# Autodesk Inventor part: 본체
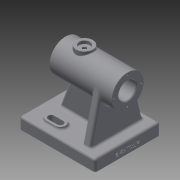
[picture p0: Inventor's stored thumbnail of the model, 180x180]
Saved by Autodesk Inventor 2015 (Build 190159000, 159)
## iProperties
Created: 2022-06
Part Number: 본체
Material: 일반
Document SubType Name: Modeling
Designer: 104-111
Density: 1 g/cm^3
Appearance: 기본값
Author: 104-111
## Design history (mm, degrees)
sketch "스케치1"
  geometry: L1 (0, 0)-(-100, 0); L2 (-100, 0)-(-100, 86); L3 (-100, 86)-(0, 86); L4 (0, 86)-(0, 0)
  constraints: 8 end point, 2 parallel, 1 horizontal, 1 perpendicular
  dimensions: "d0" = 100 distance of L1.start L1.end; "d1" = 86 distance of L3.end L1.start
extrude "돌출1" new body sketch "스케치1" distance "d2" = 15; taper "d3" = 0 deg
sketch "스케치2"
  geometry: L1 (0, 0)-(0, 86) reference; L2 (0, 86)-(-100, 86) reference; L3 (-100, 86)-(-100, 0) reference; L4 (-74, 70)-(-62, 70); L5 (-74, 63)-(-62, 63); L6 (-62, 77)-(-74, 77); L7 (-74, 16)-(-62, 16); L8 (-74, 9)-(-62, 9); L9 (-62, 23)-(-74, 23); L10 (-100, 43)-(0, 43); A1 r 7 centre (-74, 70) between (-74, 77) and (-74, 63); A2 r 7 centre (-62, 70) between (-62, 63) and (-62, 77); A3 r 7 centre (-74, 16) between (-74, 23) and (-74, 9); A4 r 7 centre (-62, 16) between (-62, 9) and (-62, 23); 2 further points
  constraints: 18 end point, 8 point on circle, 8 tangent, 4 centre point, 4 midpoint, 3 parallel, 1 horizontal
  dimensions: "d4" = 12 distance of L6.start L6.end; "d5" = 12 distance of L9.start L9.end; "d6" = 54 distance of point (-68, 16) point (-68, 70); "d7" = 16 distance from line of L2 point (-68, 70); "d8" = 26 distance from line of L3 L6.end; "d9" = 26 distance from line of L3 L8.start; "d10" = 14 distance between parallel lines of L6 L5; "d11" = 14 distance between parallel lines of L8 L9
extrude "돌출2" join sketch "스케치2" distance "d12" = 3; taper "d13" = 0 deg
sketch "스케치3"
  geometry: L1 (-74, 70)-(-62, 70); L2 (-74, 66)-(-62, 66); L3 (-62, 74)-(-74, 74); A1 r 7 centre (-62, 70) between (-62, 63) and (-62, 77) reference; A2 r 7 centre (-74, 70) between (-74, 77) and (-74, 63) reference; A3 r 4 centre (-74, 70) between (-74, 74) and (-74, 66); A4 r 4 centre (-62, 70) between (-62, 66) and (-62, 74); 2 further points
  constraints: 8 end point, 4 point on circle, 4 tangent, 2 centre point, 1 horizontal, 1 midpoint, 1 parallel
  dimensions: "d14" = 8 distance between parallel lines of L2 L3
extrude "돌출3" cut sketch "스케치3" stored distance "d15" = 3; taper "d16" = 0 deg
sketch "스케치4"
  geometry: L1 (-74, 16)-(-62, 16); L2 (-74, 20)-(-62, 20); L3 (-62, 12)-(-74, 12); A1 r 7 centre (-62, 16) between (-62, 9) and (-62, 23) reference; A2 r 7 centre (-74, 16) between (-74, 23) and (-74, 9) reference; A3 r 4 centre (-74, 16) between (-74, 20) and (-74, 12); A4 r 4 centre (-62, 16) between (-62, 12) and (-62, 20); 2 further points
  constraints: 8 end point, 4 point on circle, 4 tangent, 2 centre point, 1 horizontal, 1 midpoint, 1 parallel
  dimensions: "d17" = 8 distance between parallel lines of L2 L3
extrude "돌출4" cut sketch "스케치4" stored distance "d18" = 3; taper "d19" = 0 deg
sketch "스케치5"
  geometry: L1 (0, 0)-(0, 86) reference; L2 (-100, 86)-(-100, 0) reference; L3 (-85, 48)-(-15, 48); L4 (-15, 48)-(-15, 38); L5 (-15, 38)-(-85, 38); L6 (-85, 38)-(-85, 48); L7 (-100, 43)-(0, 43)
  constraints: 10 end point, 2 midpoint, 2 parallel, 1 horizontal, 1 perpendicular
  dimensions: "d20" = 10 distance between parallel lines of L5 L3; "d21" = 5 distance between parallel lines of L7 L3; "d22" = 15 distance between parallel lines of L2 L6; "d23" = 70 distance of L3.start L3.end
extrude "돌출5" join sketch "스케치5" distance "d24" = 57; taper "d25" = 0 deg
sketch "스케치6"
  geometry: L1 (-57, 0)-(-57, 10) reference; L2 (0, 0)-(-57, 0) reference; L3 (0, 48)-(0, -38) reference; L4 (15, -38)-(0, -38) reference; L5 (0, -38)-(0, 48) reference; L6 (-57, 5)-(21.35, 5); L7 (0, -30)-(-61.814, -15.441); L8 (0, 40)-(-61.814, 25.441); L9 (15, 48)-(0, 48) reference; L10 (-36, 0)-(0, 0); A1 r 21 centre (-57, 5) between (-61.814, -15.441) and (-61.814, 25.441); 1 further point
  constraints: 8 end point, 3 point on line, 2 horizontal, 2 point on circle, 2 tangent, 1 centre point, 1 midpoint
  dimensions: "d26" = 42 diameter of A1; "d28" = 8 distance from line of L9 L8.start; "d29" = 8 distance from line of L7.start L4
extrude "돌출6" join sketch "스케치6" distance "d30" = 10; taper "d31" = 0 deg
sketch "스케치7"
  geometry: C1 r 21 at (0, 5); A1 r 21 centre (0, 5) between (20.396, 10) and (-4.814, 25.441) reference; 1 further point
  constraints: 1 centre point, 1 coincident
  dimensions: "d32" = 42 diameter of C1
extrude "돌출7" join sketch "스케치7" distance "d33" = 15; taper "d35" = 0 deg; dims "d34" = 67, "d36" = 0
feature "면 기울기1" dims angle "d37" = 20 deg
sketch "스케치8"
  geometry: C1 r 21 at (0, 0) reference; C2 r 11.5 at (0, 0); 1 further point
  constraints: 1 centre point, 1 coincident
  dimensions: "d38" = 23 diameter of C2
extrude "돌출8" cut sketch "스케치8" distance "d39" = 20; taper "d40" = 0 deg
sketch "스케치9"
  geometry: C1 r 11.5 at (0, 0) reference; C2 r 14.5 at (0, 0); 1 further point
  constraints: 1 centre point, 1 coincident
  dimensions: "d41" = 29 diameter of C2
extrude "돌출9" cut sketch "스케치9" distance "d42" = 62; taper "d43" = 0 deg
sketch "스케치10"
  geometry: C1 r 11.5 at (0, 0) reference; 2 further points
  constraints: 1 horizontal alignment
  dimensions: "d44" = 18 distance of point (-18, 0) C1.centre
hole "구멍1" sketch "스케치10" at (-18, 0) diameter "d45" = 2.459; stored, may be unused: countersink angle "d49" = 90 deg, drill point angle "d51" = 118 deg; dims "d46" = 8, "d47" = 4, "d48" = 2, "d50" = 10
node "작업 평면1"
node "작업 평면2"
sketch "스케치12"
  geometry: L1 (82, 22)-(82, 64) reference; L2 (25, 38)-(71.677, 38) reference; L3 (25, 22.559)-(25, 38) reference; L4 (15, 22.559)-(25, 22.559) reference; L5 (15, 63.441)-(15, 22.559) reference; L6 (15, 63.441)-(25, 63.441) reference; L7 (25, 48)-(25, 63.441) reference; L8 (71.677, 48)-(25, 48) reference; L9 (0, 64)-(0, 22) reference; L10 (82, 64)-(0, 64) reference; L11 (82, 22)-(0, 22) reference; C1 r 11 at (57, 43); 2 further points; 1 other entity
  constraints: 1 centre point, 1 other
  dimensions: "d56" = 22 diameter of C1; "d57" = 25 distance from line of L1 C1.centre; "d58" = 21 distance from line of L11 C1.centre
extrude "돌출10" join sketch "스케치12" stored distance "d59" = 62; taper "d60" = 0 deg
sketch "스케치13"
  geometry: C1 r 11 at (0, 0) reference; 1 further point
hole "구멍2" sketch "스케치13" at (0, 0) diameter "d61" = 4.917; stored, may be unused: countersink angle "d65" = 90 deg, drill point angle "d67" = 118 deg; dims "d62" = 30, "d63" = 14, "d64" = 4, "d66" = 30
fillet "모깎기1" dims "d68" = 1
fillet "모깎기2" dims "d69" = 3
fillet "모깎기3" dims "d70" = 3
fillet "모깎기4" dims "d71" = 3
fillet "모깎기5" dims "d72" = 3
fillet "모깎기6" dims "d73" = 3
fillet "모깎기7" dims "d74" = 3
chamfer "모따기1" distance "d75" = 1; stored, may be unused: second distance "d76" = 2, angle "d77" = 45 deg
sketch "스케치14"
  geometry: L1 (0, 80)-(0, 0) reference; C1 r 1.23 at (-54, 40) reference; 2 further points
  constraints: 1 horizontal alignment, 1 other
  dimensions: "d80" = 6 distance from line of point (-6, 40) L1
feature "엠보싱1" sketch "스케치14" dims "d0" = 100, "d1" = 86, "d4" = 12, "d5" = 12, "d6" = 54, "d7" = 16, "d8" = 26, "d9" = 26, "d10" = 14, "d11" = 14, "d81" = 0.5, "d82" = 0
node "솔리드1"
pattern_circular "원형 패턴1" dims angle "d53" = 360 deg
mirror "대칭1"
node "투영된 루프1"
other parameters: "d55" = -96
